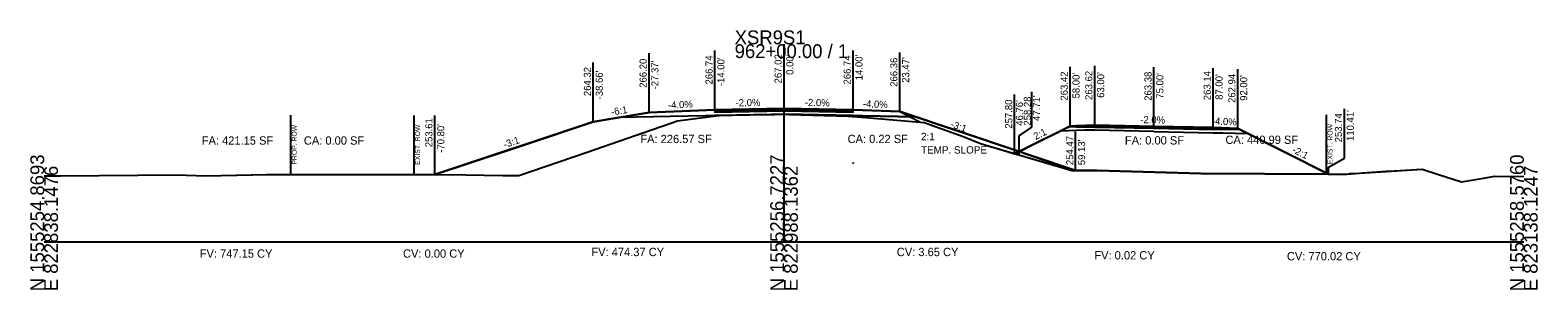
# Model space of a CAD drawing. Extents: x -26 to 823017, y -16 to 1558356.
# Drawn here: x 997.2 to 1302.8, y 990.3 to 1042.8 of the extents above; entities that cross this region are included whole.
import ezdxf

# ---------------------------------------------------------------- set-up
doc = ezdxf.new("R2010")
doc.units = 0
for name, color, linetype in [('ASPHALT_19MM1', 7, 'Continuous'), ('ASPHALT_9_5MM1', 7, 'Continuous'), ('CONST_DCH', 7, 'Continuous'), ('CONST_LV3', 7, 'Continuous'), ('Default', 7, 'Continuous'), ('Draft_XS_Grid', 7, 'Continuous'), ('DTM_CORRIDOR', 7, 'Continuous'), ('DTM_P_FINISHED_GRADE2', 7, 'Continuous'), ('DTM_TEMP_DROP', 7, 'Continuous'), ('DTM_X_GROUND', 7, 'Continuous'), ('PROFILES_DCH_2', 7, 'Continuous'), ('SLOPE_STAKES_FILL', 7, 'Continuous'), ('XS_CELL', 7, 'Continuous'), ('XS_M_SHAPES_EARTHWORK', 7, 'Continuous'), ('XS_P_ASPHALT', 7, 'Continuous'), ('XS_P_DR_GRAVEL', 7, 'Continuous'), ('XS_P_GROUND', 7, 'Continuous'), ('XS_P_NULL_POINT', 7, 'Continuous'), ('XS_P_ROW', 7, 'Continuous'), ('XS_P_SHOULDER', 7, 'Continuous'), ('XS_P_SUBGRADE_GRANULAR', 7, 'Continuous'), ('XS_P_SUBGRADE_MILLING', 7, 'Continuous'), ('XS_P_SUBGRADE_UNDERCUT', 7, 'Continuous'), ('XS_P_TX_CLEARZONE', 7, 'Continuous'), ('XS_P_TX_FS_BS', 7, 'Continuous'), ('XS_SHEET_EW_TX_AREA', 7, 'Continuous'), ('XS_SHEET_EW_TX_VOLUME', 7, 'Continuous'), ('XS_X_ROW', 7, 'Continuous')]:
    doc.layers.add(name, color=color, linetype=linetype)

msp = doc.modelspace()

# ---------------------------------------------------------------- linework, layer by layer
at = {"layer": 'ASPHALT_19MM1'}
for points in [[(1136, 1026.45), (1136, 1026.24), (1150, 1026.52), (1150, 1026.52), (1150, 1026.52), (1164, 1026.24), (1164, 1026.45), (1164, 1026.45), (1150, 1026.73), (1150, 1026.73), (1150, 1026.73), (1136, 1026.45), (1136, 1026.45)], [(1213, 1023.25), (1225, 1023.01), (1237, 1022.77), (1237, 1022.98), (1225, 1023.22), (1213, 1023.46), (1213, 1023.25)]]:
    msp.add_lwpolyline(points, dxfattribs=at)
at = {"layer": 'ASPHALT_9_5MM1'}
msp.add_lwpolyline([(1136, 1026.74), (1136, 1026.61), (1150, 1026.89), (1150, 1026.89), (1150, 1026.89), (1164, 1026.61), (1164, 1026.74), (1164, 1026.74), (1150, 1027.02), (1150, 1027.02), (1150, 1027.02), (1136, 1026.74), (1136, 1026.74)], dxfattribs=at)
at = {"layer": 'CONST_DCH'}
msp.add_lwpolyline([(1213, 1023.46), (1225, 1023.22), (1237, 1022.98), (1237, 1023.14), (1225, 1023.38), (1213, 1023.62), (1213, 1023.46)], dxfattribs=at)
at = {"layer": 'CONST_LV3'}
for points in [[(1111.34, 1024.32), (1116.5, 1025.18), (1116.5, 1025.18)], [(1150, 1027.02), (1164, 1026.74)], [(1173.47, 1026.36), (1164, 1026.74), (1164, 1026.74)], [(1196.76, 1017.8), (1199.58, 1019.21), (1208, 1023.42), (1211.75, 1023.57), (1213, 1023.62)], [(1197.71, 1018.28), (1197.71, 1018.28), (1199.58, 1019.21), (1200, 1019.42), (1208, 1023.42), (1209.25, 1023.47), (1213, 1023.62), (1222.01, 1023.44), (1225, 1023.38), (1227.99, 1023.32), (1237, 1023.14), (1238.25, 1023.09), (1242, 1022.94), (1246.18, 1020.85), (1260.41, 1013.74), (1264.11, 1013.72), (1264.14, 1013.72), (1264.76, 1013.81), (1266.68, 1013.93), (1267.31, 1014), (1272.08, 1014.29), (1272.6, 1014.33), (1279.36, 1014.72), (1282.67, 1013.64), (1287.35, 1012.16), (1291.83, 1012.87), (1294.14, 1013.28), (1300, 1013.25)], [(1242, 1022.94), (1260.41, 1013.74)], [(1164, 1016.09), (1164, 1015.96), (1164, 1016.03), (1164, 1016.03)], [(1000, 1013.38), (1003.32, 1013.39), (1026.83, 1013.55), (1032.8, 1013.34), (1045, 1013.64), (1045.38, 1013.65), (1045.39, 1013.65), (1072.76, 1013.61), (1073.2, 1013.61), (1073.63, 1013.61), (1074.42, 1013.61), (1075.9, 1013.61), (1079.2, 1013.61), (1079.2, 1013.61)]]:
    msp.add_lwpolyline(points, dxfattribs=at)
at = {"layer": 'Default'}
msp.add_lwpolyline([(1136, 1026.61), (1136, 1026.45), (1150, 1026.73), (1150, 1026.73), (1150, 1026.73), (1164, 1026.45), (1164, 1026.61), (1164, 1026.61), (1150, 1026.89), (1150, 1026.89), (1150, 1026.89), (1136, 1026.61), (1136, 1026.61)], dxfattribs=at)
at = {"layer": 'DTM_P_FINISHED_GRADE2'}
msp.add_lwpolyline([(1079.2, 1013.61), (1097.56, 1019.73), (1111.34, 1024.32), (1122.63, 1026.2), (1136, 1026.74), (1150, 1027.02), (1164, 1026.74), (1173.47, 1026.36), (1197.71, 1018.28)], dxfattribs=at)
at = {"layer": 'DTM_X_GROUND'}
for points in [[(1000, 1013.38), (1003.32, 1013.39), (1026.83, 1013.55), (1032.8, 1013.34), (1045, 1013.64), (1045.38, 1013.65), (1045.39, 1013.65), (1072.76, 1013.61), (1073.2, 1013.61), (1073.63, 1013.61), (1074.42, 1013.61), (1075.9, 1013.61), (1079.2, 1013.61), (1079.2, 1013.61), (1094.54, 1018.72), (1097.56, 1019.73), (1111.34, 1024.32), (1111.34, 1024.32), (1122.63, 1026.2), (1122.63, 1026.2), (1136, 1026.74), (1136, 1026.74), (1136, 1026.74), (1150, 1027.02), (1150, 1027.02), (1164, 1026.74), (1164, 1026.74), (1173.47, 1026.36), (1173.47, 1026.36), (1173.47, 1026.36), (1173.47, 1026.36), (1197.71, 1018.28), (1197.71, 1018.28), (1199.58, 1019.21), (1200, 1019.42), (1208, 1023.42), (1209.25, 1023.47), (1213, 1023.62), (1222.01, 1023.44), (1225, 1023.38), (1227.99, 1023.32), (1237, 1023.14), (1238.25, 1023.09), (1242, 1022.94), (1246.18, 1020.85), (1260.41, 1013.74), (1264.11, 1013.72), (1264.14, 1013.72), (1264.76, 1013.81), (1266.68, 1013.93), (1267.31, 1014), (1272.08, 1014.29), (1272.6, 1014.33), (1279.36, 1014.72), (1282.67, 1013.64), (1287.35, 1012.16), (1291.83, 1012.87), (1294.14, 1013.28), (1300, 1013.25)], [(1000, 1013.38), (1003.32, 1013.39), (1026.83, 1013.55), (1032.8, 1013.34), (1045.38, 1013.65), (1073.2, 1013.61), (1085.42, 1013.6), (1092.97, 1013.45), (1096.21, 1013.43), (1109.87, 1018.1), (1128.43, 1024.49), (1136.72, 1025.56), (1137.29, 1025.64), (1148.11, 1025.81), (1150.11, 1025.84), (1151.08, 1025.81), (1162.98, 1025.46), (1166.58, 1025.17), (1178.45, 1024.19), (1186.53, 1021.24), (1189.84, 1019.93), (1194.15, 1018.65), (1208.36, 1014.48), (1211.53, 1014.44), (1213.5, 1014.47), (1234.49, 1013.86), (1264.14, 1013.72), (1266.68, 1013.89), (1272.08, 1014.24), (1279.36, 1014.72), (1282.67, 1013.64), (1287.35, 1012.16), (1291.83, 1012.87), (1294.14, 1013.28), (1300, 1013.25)], [(1000, 1013.38), (1003.32, 1013.39), (1026.83, 1013.55), (1032.8, 1013.34), (1045.38, 1013.65), (1073.2, 1013.61), (1085.42, 1013.6), (1092.97, 1013.45), (1096.21, 1013.43), (1109.87, 1018.1), (1128.43, 1024.49), (1136.72, 1025.56), (1137.29, 1025.64), (1148.11, 1025.81), (1150.11, 1025.84), (1151.08, 1025.81), (1162.98, 1025.46), (1166.58, 1025.17), (1178.45, 1024.19), (1186.53, 1021.24), (1189.84, 1019.93), (1191.42, 1019.46), (1194.15, 1018.61), (1196.76, 1017.8), (1197.38, 1018.11), (1199.58, 1019.21), (1208, 1023.42), (1209.25, 1023.47), (1213, 1023.62), (1222.01, 1023.44), (1225, 1023.38), (1227.99, 1023.32), (1237, 1023.14), (1238.25, 1023.09), (1242, 1022.94), (1246.18, 1020.85), (1260.41, 1013.74), (1264.11, 1013.72), (1264.14, 1013.72), (1264.76, 1013.81), (1266.68, 1013.93), (1267.31, 1014), (1272.08, 1014.29), (1272.6, 1014.33), (1279.36, 1014.72), (1282.67, 1013.64), (1287.35, 1012.16), (1291.83, 1012.87), (1294.14, 1013.28), (1300, 1013.25)]]:
    msp.add_lwpolyline(points, dxfattribs=at)
at = {"layer": 'XS_CELL'}
for p, q in [((1150, 1000), (1150, 1040)), ((1000, 1000), (1150, 1000)), ((1150, 1000), (1300, 1000))]:
    msp.add_line(p, q, dxfattribs=at)
at = {"layer": 'XS_M_SHAPES_EARTHWORK'}
for points in [[(1079.2, 1013.61), (1085.42, 1013.6), (1092.97, 1013.45), (1096.21, 1013.43), (1109.87, 1018.1), (1128.43, 1024.49), (1136.72, 1025.56), (1136.91, 1025.59), (1136, 1025.57), (1134, 1025.53), (1116.5, 1025.18), (1111.34, 1024.32)], [(1136.91, 1025.59), (1137.29, 1025.64), (1147.42, 1025.8)], [(1147.42, 1025.8), (1148.11, 1025.81), (1150.11, 1025.84), (1151.08, 1025.81), (1162.98, 1025.46), (1166.58, 1025.17), (1178.45, 1024.19), (1186.53, 1021.24), (1189.84, 1019.93), (1194.15, 1018.65), (1197.71, 1017.61), (1197.71, 1018.28), (1176.59, 1025.32), (1166, 1025.53), (1164, 1025.57), (1150, 1025.85)]]:
    msp.add_lwpolyline(points, close=True, dxfattribs=at)
at = {"layer": 'XS_P_DR_GRAVEL'}
for points in [[(1211.75, 1023.57), (1208, 1023.42), (1207.96, 1023.4), (1207.86, 1023.35), (1209.14, 1023.32), (1213, 1023.25), (1213, 1023.53), (1213, 1023.62), (1211.75, 1023.57)], [(1238.25, 1023.09), (1242, 1022.94), (1242.14, 1022.87), (1242.57, 1022.66), (1238.39, 1022.74), (1237, 1022.77), (1237, 1023.05), (1237, 1023.14), (1238.25, 1023.09)]]:
    msp.add_lwpolyline(points, dxfattribs=at)
at = {"layer": 'XS_P_GROUND'}
msp.add_line((1173.47, 1026.36), (1177.68, 1024.26), dxfattribs=at)
for points in [[(1122.63, 1026.2), (1111.34, 1024.32), (1079.2, 1013.61)], [(1197.71, 1018.28), (1173.47, 1026.36), (1173.47, 1026.36)], [(1209.13, 1014.47), (1173.47, 1026.36), (1173.47, 1026.36)], [(1208, 1023.42), (1196.76, 1017.8)], [(1242, 1022.94), (1260.41, 1013.74)], [(1260.41, 1013.74), (1234.49, 1013.86), (1234.49, 1013.86), (1213.5, 1014.47), (1213.5, 1014.47), (1211.53, 1014.44), (1209.13, 1014.47), (1209.13, 1014.47)], [(1209.13, 1014.47), (1209.13, 1014.47), (1211.53, 1014.44), (1213.5, 1014.47), (1213.5, 1014.47), (1234.49, 1013.86), (1234.49, 1013.86), (1260.41, 1013.74)]]:
    msp.add_lwpolyline(points, dxfattribs=at)
at = {"layer": 'XS_P_ROW'}
msp.add_line((1050, 1013.64), (1050, 1025.64), dxfattribs=at)
at = {"layer": 'XS_P_SHOULDER'}
for points in [[(1136, 1026.74), (1122.63, 1026.2)], [(1164, 1026.74), (1173.47, 1026.36)], [(1208, 1023.42), (1211.75, 1023.57), (1213, 1023.62)], [(1242, 1022.94), (1238.25, 1023.09), (1237, 1023.14)]]:
    msp.add_lwpolyline(points, dxfattribs=at)
at = {"layer": 'XS_P_SUBGRADE_GRANULAR'}
for points in [[(1136, 1025.57), (1134, 1025.53), (1116.5, 1025.18)], [(1136, 1025.57), (1150, 1025.85), (1150, 1025.85)], [(1164, 1025.57), (1150, 1025.85), (1150, 1025.85)], [(1164, 1025.57), (1166, 1025.53), (1176.59, 1025.32)], [(1213, 1022.58), (1211, 1022.62), (1206, 1022.42)], [(1225, 1022.34), (1213, 1022.58)], [(1225, 1022.34), (1237, 1022.1)], [(1237, 1022.1), (1239, 1022.06), (1243.96, 1021.96)]]:
    msp.add_lwpolyline(points, dxfattribs=at)
at = {"layer": 'XS_P_SUBGRADE_UNDERCUT'}
msp.add_lwpolyline([(1208.59, 1014.52), (1209.3, 1014.51), (1215.72, 1014.42), (1234.49, 1013.86), (1249.32, 1013.79), (1260.41, 1013.74), (1242, 1022.94), (1237, 1023.14), (1227.99, 1023.32), (1222.01, 1023.44), (1213, 1023.62), (1209.25, 1023.47), (1208, 1023.42), (1197.71, 1018.28)], close=True, dxfattribs=at)
at = {"layer": 'XS_P_TX_CLEARZONE'}
for p, q in [((1111.34, 1024.32), (1111.34, 1036.32)), ((1122.63, 1026.2), (1122.63, 1038.2)), ((1136, 1026.74), (1136, 1038.74)), ((1150, 1027.02), (1150, 1039.02)), ((1164, 1026.74), (1164, 1038.74)), ((1173.47, 1026.36), (1173.47, 1038.36)), ((1208, 1023.42), (1208, 1035.42)), ((1213, 1023.62), (1213, 1035.62)), ((1225, 1023.38), (1225, 1035.38)), ((1237, 1023.14), (1237, 1035.14)), ((1242, 1022.94), (1242, 1034.94)), ((1200.26, 1023.19), (1200.26, 1030.39)), ((1196.76, 1017.8), (1196.76, 1029.8)), ((1079.2, 1013.61), (1079.2, 1025.61)), ((1263.61, 1016.94), (1263.61, 1026.9)), ((1197.71, 1021.46), (1200.26, 1023.19)), ((1197.71, 1018.28), (1197.71, 1021.46)), ((1209.13, 1014.47), (1209.13, 1022.25)), ((1260.41, 1015.13), (1263.61, 1016.94)), ((1260.41, 1013.74), (1260.41, 1015.13))]:
    msp.add_line(p, q, dxfattribs=at)
at = {"layer": 'XS_X_ROW'}
for p, q in [((1075, 1013.61), (1075, 1025.61)), ((1260, 1013.74), (1260, 1025.74))]:
    msp.add_line(p, q, dxfattribs=at)

# ---------------------------------------------------------------- texts
at = {"layer": 'CONST_DCH'}
for p in [(1196.68, 1017.68), (1260.33, 1013.62), (1260.33, 1013.62)]:
    msp.add_text('X', height=0.24, dxfattribs=at).set_placement(p)
at = {"layer": 'Draft_XS_Grid'}
msp.add_text('-', height=0.0001, dxfattribs=at).set_placement((1000, 1000))
at = {"layer": 'DTM_CORRIDOR'}
for p in [(1212.92, 1023.5), (1224.92, 1023.26), (1236.92, 1023.02)]:
    msp.add_text('X', height=0.24, dxfattribs=at).set_placement(p)
at = {"layer": 'DTM_TEMP_DROP'}
for p in [(1149.92, 1026.9), (1135.92, 1026.62), (1163.92, 1026.62)]:
    msp.add_text('X', height=0.24, dxfattribs=at).set_placement(p)
at = {"layer": 'PROFILES_DCH_2'}
for p in [(1173.4, 1026.24), (1209.06, 1014.35), (1260.33, 1013.62)]:
    msp.add_text('X', height=0.24, dxfattribs=at).set_placement(p)
at = {"layer": 'SLOPE_STAKES_FILL'}
for p in [(1197.64, 1018.16), (1079.12, 1013.49)]:
    msp.add_text('X', height=0.24, dxfattribs=at).set_placement(p)
at = {"layer": 'XS_CELL'}
for s, p in [('XSR9S1', (1140, 1040)), ('962+00.00 / 1', (1140, 1037.2))]:
    msp.add_text(s, height=2.8, dxfattribs=at).set_placement(p)
for s, p in [('N 1555254.8693', (1000, 990)), ('E 822838.1476', (1002.8, 990)), ('N 1555256.7227', (1150, 990)), ('E 822988.1362', (1152.8, 990)), ('N 1555258.5760', (1300, 990)), ('E 823138.1247', (1302.8, 990))]:
    msp.add_text(s, height=2.8, rotation=90, dxfattribs=at).set_placement(p)
at = {"layer": 'XS_P_ASPHALT'}
for p in [(1196.68, 1017.68), (1260.33, 1013.62)]:
    msp.add_text('X', height=0.24, dxfattribs=at).set_placement(p)
at = {"layer": 'XS_P_GROUND'}
for s, p in [('2:1', (1177.78, 1020.57)), ('TEMP. SLOPE', (1177.78, 1017.87))]:
    msp.add_text(s, height=1.5, dxfattribs=at).set_placement(p)
at = {"layer": 'XS_P_NULL_POINT'}
for p in [(1197.64, 1018.16), (1079.12, 1013.49)]:
    msp.add_text('X', height=0.24, dxfattribs=at).set_placement(p)
at = {"layer": 'XS_P_ROW'}
msp.add_text('PROP. ROW', height=1, rotation=90, dxfattribs=at).set_placement((1051.2, 1015.64))
at = {"layer": 'XS_P_SHOULDER'}
for p in [(1111.26, 1024.2), (1207.92, 1023.3), (1241.92, 1022.82)]:
    msp.add_text('X', height=0.24, dxfattribs=at).set_placement(p)
at = {"layer": 'XS_P_SUBGRADE_MILLING'}
for p in [(1122.55, 1026.08), (1173.4, 1026.24)]:
    msp.add_text('X', height=0.24, dxfattribs=at).set_placement(p)
at = {"layer": 'XS_P_TX_CLEARZONE'}
for s, p in [('266.20', (1122.15, 1031.19)), ("-27.37'", (1124.55, 1030.86)), ('266.74', (1135.52, 1031.85)), ("-14.00'", (1137.92, 1031.53)), ('267.02', (1149.52, 1032.08)), ("0.00'", (1151.92, 1033.81)), ('266.74', (1163.52, 1031.85)), ("14.00'", (1165.92, 1032.71)), ('266.36', (1172.99, 1031.39)), ("23.47'", (1175.39, 1032.19)), ('264.32', (1110.86, 1029.5)), ("-38.66'", (1113.26, 1028.84)), ('263.42', (1207.52, 1028.6)), ("58.00'", (1209.92, 1029.03)), ('263.62', (1212.52, 1028.73)), ("63.00'", (1214.92, 1029.16)), ('263.38', (1224.52, 1028.56)), ("75.00'", (1226.92, 1028.99)), ('263.14', (1236.52, 1028.68)), ("87.00'", (1238.92, 1028.75)), ('262.94', (1241.52, 1028.12)), ("92.00'", (1243.92, 1028.55)), ('257.80', (1196.28, 1022.92)), ("46.76'", (1198.45, 1023.5)), ('258.28', (1200.06, 1023.53)), ("47.71'", (1201.9, 1024.48)), ('253.61', (1078.72, 1019.15)), ('253.74', (1263.13, 1020.15)), ("110.41'", (1265.53, 1020.42)), ("-70.80'", (1081.12, 1018.04)), ('254.47', (1208.65, 1015.55)), ("59.13'", (1211.05, 1015.52))]:
    msp.add_text(s, height=1.44, rotation=90, dxfattribs=at).set_placement(p)
at = {"layer": 'XS_P_TX_FS_BS'}
for s, rotation, p in [('-6:1', 9.4642, (1115.06, 1025.55)), ('-4.0%', 2.2906, (1126.5, 1026.96)), ('-2.0%', 1.1458, (1140.2, 1027.42)), ('-2.0%', 358.8542, (1154.22, 1027.53)), ('-4.0%', 357.7094, (1165.97, 1027.26)), ('-3:1', 339.8273, (1183.62, 1023.27)), ('-2.0%', 358.8542, (1222.22, 1024.04)), ('-4.0%', 357.7094, (1236.73, 1023.75)), ('-3:1', 18.4332, (1093.36, 1018.96)), ('2:1', 26.5651, (1201.02, 1020.6)), ('-2:1', 333.4349, (1252.89, 1018.17))]:
    msp.add_text(s, height=1.44, rotation=rotation, dxfattribs=at).set_placement(p)
at = {"layer": 'XS_SHEET_EW_TX_AREA'}
for s, p in [('FA: 421.15 SF', (1031.95, 1019.68)), ('CA: 0.00 SF', (1052.65, 1019.68)), ('FA: 226.57 SF', (1120.87, 1020)), ('CA: 0.22 SF', (1162.89, 1020)), ('FA: 0.00 SF', (1219.12, 1019.71)), ('CA: 440.99 SF', (1239.5, 1019.83))]:
    msp.add_text(s, height=1.68, dxfattribs=at).set_placement(p)
at = {"layer": 'XS_SHEET_EW_TX_VOLUME'}
for s, p in [('FV: 747.15 CY', (1031.55, 996.8)), ('CV: 0.00 CY', (1072.76, 996.8)), ('FV: 474.37 CY', (1110.95, 997.12)), ('CV: 3.65 CY', (1172.87, 997.12)), ('FV: 0.02 CY', (1212.92, 996.45)), ('CV: 770.02 CY', (1251.96, 996.26))]:
    msp.add_text(s, height=1.68, dxfattribs=at).set_placement(p)
at = {"layer": 'XS_X_ROW'}
for p in [(1076.2, 1015.61), (1261.2, 1015.74)]:
    msp.add_text('EXIST. ROW', height=1, rotation=90, dxfattribs=at).set_placement(p)

doc.saveas('drawing.dxf')
